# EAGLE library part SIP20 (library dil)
SOCKET Single In Line
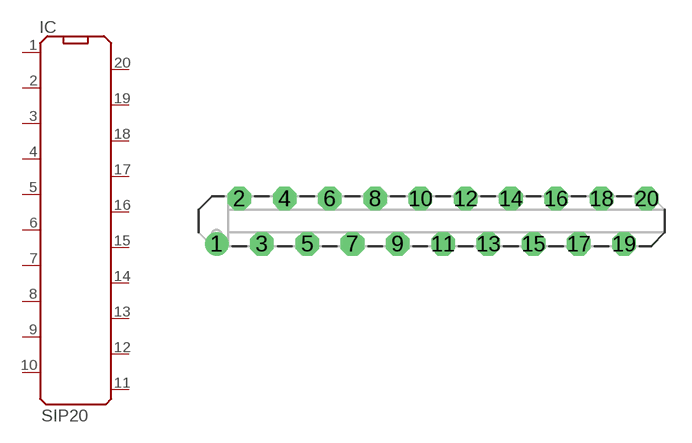
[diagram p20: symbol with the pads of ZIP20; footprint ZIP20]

Designator prefix IC

## SIP20  [ZIP20]
1  1  pas
2  2  pas
3  3  pas
4  4  pas
5  5  pas
6  6  pas
7  7  pas
8  8  pas
9  9  pas
10  10  pas
11  11  pas
12  12  pas
13  13  pas
14  14  pas
15  15  pas
16  16  pas
17  17  pas
18  18  pas
19  19  pas
20  20  pas

## Footprint ZIP20 (pad centres in mm)
SOCKET Single In Line
drill 0.813 round: 1 -12.065,-1.27
drill 0.813 octagon: 2 -10.795,1.27; 3 -9.525,-1.27; 4 -8.255,1.27; 5 -6.985,-1.27; 6 -5.715,1.27; 7 -4.445,-1.27; 8 -3.175,1.27; 9 -1.905,-1.27; 10 -0.635,1.27; 11 0.635,-1.27; 12 1.905,1.27; 13 3.175,-1.27; 14 4.445,1.27; 15 5.715,-1.27; 16 6.985,1.27; 17 8.255,-1.27; 18 9.525,1.27; 19 10.795,-1.27; 20 12.065,1.27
